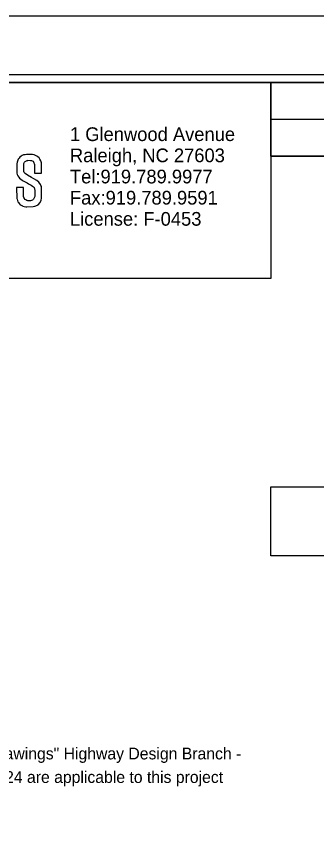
# Model space of a CAD drawing. Extents: x 1537922 to 1539606, y 409903 to 410998.
# Drawn here: x 1539302.4 to 1539404.5, y 410723.4 to 410998.4 of the extents above; entities that cross this region are included whole.
import ezdxf

# ---------------------------------------------------------------- set-up
doc = ezdxf.new("R2010")
doc.units = 0
for name, color, linetype in [('Default', 7, 'Continuous'), ('Old_Level_2', 7, 'Continuous'), ('Old_Level_58', 7, 'Continuous'), ('Sheet Cutting Line CELL', 7, 'Continuous'), ('Sheet Plan CELL', 7, 'Continuous'), ('Sheet Plot Border Inside CELL', 7, 'Continuous'), ('Sheet Plot Border Outside CELL', 7, 'Continuous'), ('Sheet Sticker Exception Certification CELL', 7, 'Continuous')]:
    doc.layers.add(name, color=color, linetype=linetype)

msp = doc.modelspace()

# ---------------------------------------------------------------- linework, layer by layer
at = {"layer": 'Default'}
msp.add_lwpolyline([(1539308.59, 410945), (1539310.9, 410945.01), (1539310.9, 410948.48), (1539310.7, 410949.19), (1539310.42, 410949.78), (1539310.12, 410950.17), (1539309.75, 410950.52), (1539309.31, 410950.8), (1539308.89, 410950.98), (1539308.89, 410950.98), (1539308.43, 410951.17), (1539307.94, 410951.29), (1539307.62, 410951.37), (1539305.87, 410951.34), (1539305.35, 410951.25), (1539304.89, 410951.17), (1539304.43, 410950.93), (1539304.02, 410950.72), (1539303.63, 410950.43), (1539303.32, 410950.12), (1539303.08, 410949.75), (1539302.88, 410949.36), (1539302.63, 410948.66), (1539302.58, 410948.15), (1539302.58, 410944.98), (1539302.69, 410944.5), (1539302.92, 410944.01), (1539303.21, 410943.6), (1539303.51, 410943.29), (1539303.96, 410942.94), (1539304.41, 410942.59), (1539304.69, 410942.37), (1539305.18, 410942.15), (1539305.66, 410941.92), (1539306.05, 410941.67), (1539306.49, 410941.38), (1539307.02, 410941.12), (1539307.45, 410940.9), (1539307.88, 410940.58), (1539308.19, 410940.29), (1539308.44, 410940.05), (1539308.6, 410939.57), (1539308.69, 410939.27), (1539308.65, 410937.03), (1539308.49, 410936.55), (1539308.25, 410936.13), (1539307.92, 410935.84), (1539307.57, 410935.68), (1539307.22, 410935.6), (1539306.26, 410935.58), (1539305.94, 410935.67), (1539305.61, 410935.87), (1539305.28, 410936.06), (1539305.14, 410936.4), (1539305, 410936.73), (1539304.89, 410937), (1539304.85, 410940.11), (1539302.51, 410940.08), (1539302.55, 410936.37), (1539302.67, 410936.09), (1539302.94, 410935.23), (1539303.12, 410934.94), (1539303.37, 410934.62), (1539303.75, 410934.24), (1539304.05, 410934.05), (1539304.49, 410933.87), (1539304.65, 410933.8), (1539305.08, 410933.62), (1539305.61, 410933.57), (1539306.01, 410933.53), (1539308.15, 410933.58), (1539308.74, 410933.72), (1539309.57, 410934.1), (1539309.85, 410934.22), (1539310.47, 410935.01), (1539310.8, 410935.8), (1539310.96, 410936.51), (1539310.9, 410939.93), (1539310.9, 410940.41), (1539310.77, 410940.78), (1539310.57, 410941.14), (1539310.04, 410941.9), (1539309.33, 410942.45), (1539308.35, 410943.03), (1539307.61, 410943.48), (1539306.14, 410944.24), (1539305.39, 410944.8), (1539305.06, 410945.23), (1539304.98, 410945.51), (1539304.91, 410945.79), (1539304.95, 410948.22), (1539305.08, 410948.48), (1539305.2, 410948.73), (1539305.38, 410948.89), (1539305.61, 410949.08), (1539305.87, 410949.19), (1539306.13, 410949.3), (1539306.28, 410949.27), (1539306.29, 410949.34), (1539307.25, 410949.33), (1539307.53, 410949.22), (1539307.8, 410949.11), (1539308.08, 410949), (1539308.21, 410948.8), (1539308.4, 410948.53), (1539308.49, 410948.25), (1539308.58, 410947.97), (1539308.57, 410947.67)], close=True, dxfattribs=at)
at = {"layer": 'Old_Level_58'}
msp.add_lwpolyline([(1539188.77, 410975.85), (1539388.82, 410975.85), (1539388.82, 410909.16), (1539188.77, 410909.16)], close=True, dxfattribs=at)
at = {"layer": 'Sheet Cutting Line CELL'}
msp.add_line((1539605.87, 410998.35), (1537922.37, 410998.35), dxfattribs=at)
at = {"layer": 'Sheet Plan CELL'}
for p, q in [((1539388.82, 410963.3), (1539588.87, 410963.3)), ((1539388.82, 410950.8), (1539588.87, 410950.8)), ((1539388.82, 410950.8), (1539588.87, 410950.8))]:
    msp.add_line(p, q, dxfattribs=at)
for points in [[(1539588.87, 410975.85), (1538088.87, 410975.85), (1538088.87, 409925.85), (1539588.87, 409925.85)], [(1539388.82, 410975.85), (1539588.87, 410975.85), (1539588.87, 410950.8), (1539388.82, 410950.8)]]:
    msp.add_lwpolyline(points, close=True, dxfattribs=at)
at = {"layer": 'Sheet Plot Border Inside CELL'}
msp.add_lwpolyline([(1537935.37, 409923.35), (1539601.37, 409923.35), (1539601.37, 410978.35), (1537935.37, 410978.35)], close=True, dxfattribs=at)
at = {"layer": 'Sheet Plot Border Outside CELL'}
msp.add_lwpolyline([(1537922.37, 409903.35), (1539605.87, 409903.35), (1539605.87, 410998.35), (1537922.37, 410998.35)], close=True, dxfattribs=at)
at = {"layer": 'Sheet Sticker Exception Certification CELL'}
for p, q in [((1539388.83, 410814.81), (1539388.83, 410838.31)), ((1539388.83, 410838.31), (1539588.87, 410838.31)), ((1539588.87, 410814.81), (1539388.83, 410814.81))]:
    msp.add_line(p, q, dxfattribs=at)

# ---------------------------------------------------------------- texts
at = {"layer": 'Default'}
for s, p in [('The following Roadway Standards as appear in "Roadway Standard Drawings" Highway Design Branch -', (1539130.32, 410745.62)), ('N. C. Department of Transportation - Raleigh, N. C., Dated January, 2024 are applicable to this project', (1539130.32, 410737.62))]:
    msp.add_text(s, height=4, dxfattribs=at).set_placement(p)
at = {"layer": 'Old_Level_2'}
for s, p in [('1 Glenwood Avenue', (1539320.61, 410955.89)), ('Raleigh, NC 27603', (1539320.61, 410948.69)), ('Tel:919.789.9977 ', (1539320.61, 410941.49)), ('Fax:919.789.9591', (1539320.61, 410934.3)), ('License: F-0453', (1539320.61, 410927.1))]:
    msp.add_text(s, height=4.6576, rotation=360, dxfattribs=at).set_placement(p)

doc.saveas('drawing.dxf')
